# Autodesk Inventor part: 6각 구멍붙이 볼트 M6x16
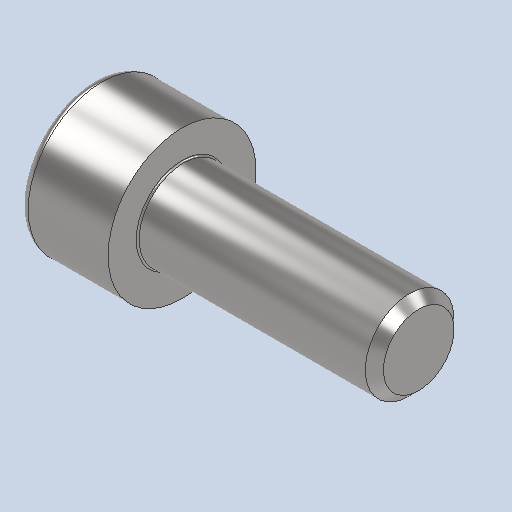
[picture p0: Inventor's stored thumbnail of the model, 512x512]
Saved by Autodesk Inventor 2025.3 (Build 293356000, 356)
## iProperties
Created: 2025-10
Part Number: 6각 구멍붙이 볼트 M6x16
Material: 강철, 연강
Description: 6각머리 태핑 나사
Document SubType Name: Modeling
Designer: PC-15
Density: 7.85 g/cm^3
Appearance: 기본값
Author: jhkim
Sending System: Autodesk Inventor 2026
Preprocessor: ST-DEVELOPER v20.1
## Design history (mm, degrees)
feature "Solid1"
node "솔리드1"
